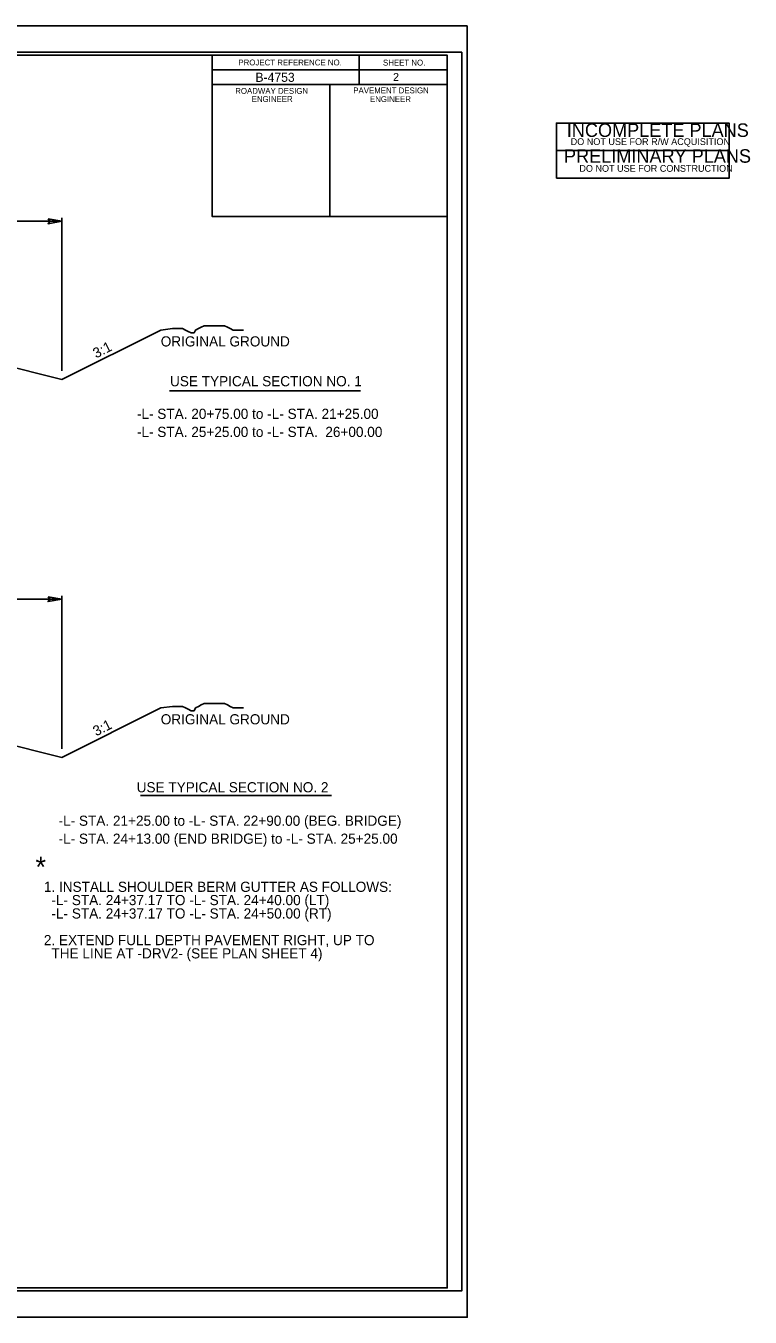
# Model space of a CAD drawing. Extents: x 1804008 to 1804260, y 659269 to 659379.
# Drawn here: x 1804198.7 to 1804260.4, y 659269.4 to 659379.4 of the extents above; entities that cross this region are included whole.
import ezdxf

# ---------------------------------------------------------------- set-up
doc = ezdxf.new("R2010")
doc.units = 0
for name, color, linetype in [('Old_Level_1', 7, 'Continuous'), ('Prop Dimension', 7, 'Continuous'), ('Sheet Cutting Line CELL', 7, 'Continuous'), ('Sheet Data Field CELL', 7, 'Continuous'), ('Sheet Plot Border Inside CELL', 7, 'Continuous'), ('Sheet Plot Border Outside CELL', 7, 'Continuous'), ('Sheet Sticker Incomplete CELL', 7, 'Continuous'), ('Sheet Sticker Preliminary CELL', 7, 'Continuous'), ('Sheet Typical CELL', 7, 'Continuous'), ('Typical Hinge Slope Arterial CELL', 7, 'Continuous'), ('Typical Terminator CELL', 7, 'Continuous')]:
    doc.layers.add(name, color=color, linetype=linetype)

msp = doc.modelspace()

# ---------------------------------------------------------------- linework, layer by layer
at = {"layer": 'Old_Level_1'}
for p, q in [((1804189.79, 659352.24), (1804201.79, 659349.24)), ((1804189.79, 659320.04), (1804201.79, 659317.04))]:
    msp.add_line(p, q, dxfattribs=at)
at = {"layer": 'Prop Dimension'}
for p, q in [((1804189.79, 659362.71), (1804201.79, 659362.71)), ((1804201.79, 659349.95), (1804201.79, 659363.01)), ((1804210.95, 659348.27), (1804227.21, 659348.27)), ((1804189.79, 659330.52), (1804201.79, 659330.52)), ((1804201.79, 659317.76), (1804201.79, 659330.81)), ((1804208.47, 659313.78), (1804224.73, 659313.78))]:
    msp.add_line(p, q, dxfattribs=at)
at = {"layer": 'Sheet Cutting Line CELL'}
for p, q in [((1804236.29, 659379.35), (1804067.89, 659379.35)), ((1804067.89, 659269.35), (1804236.29, 659269.35))]:
    msp.add_line(p, q, dxfattribs=at)
at = {"layer": 'Sheet Plot Border Inside CELL'}
msp.add_lwpolyline([(1804235.84, 659377.11), (1804069.19, 659377.11), (1804069.19, 659271.6), (1804235.84, 659271.6)], close=True, dxfattribs=at)
at = {"layer": 'Sheet Plot Border Outside CELL'}
msp.add_lwpolyline([(1804236.29, 659379.35), (1804067.89, 659379.35), (1804067.89, 659269.35), (1804236.29, 659269.35)], close=True, dxfattribs=at)
at = {"layer": 'Sheet Sticker Incomplete CELL'}
msp.add_lwpolyline([(1804243.88, 659368.72), (1804243.88, 659371.07), (1804258.58, 659371.07), (1804258.58, 659368.72)], close=True, dxfattribs=at)
at = {"layer": 'Sheet Sticker Preliminary CELL'}
msp.add_lwpolyline([(1804243.88, 659366.37), (1804243.88, 659368.72), (1804258.58, 659368.72), (1804258.58, 659366.37)], close=True, dxfattribs=at)
at = {"layer": 'Sheet Typical CELL'}
for p, q in [((1804227.09, 659376.85), (1804227.09, 659374.35)), ((1804214.59, 659375.6), (1804234.59, 659375.6)), ((1804224.59, 659374.35), (1804224.59, 659363.1))]:
    msp.add_line(p, q, dxfattribs=at)
for points in [[(1804234.59, 659376.85), (1804084.59, 659376.85), (1804084.59, 659271.85), (1804234.59, 659271.85)], [(1804214.59, 659376.85), (1804234.59, 659376.85), (1804234.59, 659374.35), (1804214.59, 659374.35)], [(1804214.59, 659374.35), (1804224.59, 659374.35), (1804224.59, 659363.1), (1804214.59, 659363.1)], [(1804224.59, 659374.35), (1804234.59, 659374.35), (1804234.59, 659363.1), (1804224.59, 659363.1)]]:
    msp.add_lwpolyline(points, close=True, dxfattribs=at)
at = {"layer": 'Typical Hinge Slope Arterial CELL'}
for p, q in [((1804210.2, 659353.44), (1804201.79, 659349.24)), ((1804210.2, 659321.25), (1804201.79, 659317.04))]:
    msp.add_line(p, q, dxfattribs=at)
for points in [[(1804210.2, 659353.44), (1804211.19, 659353.57), (1804211.44, 659353.57), (1804211.81, 659353.57), (1804212.05, 659353.57), (1804212.3, 659353.44), (1804212.54, 659353.32), (1804212.79, 659353.2), (1804213.04, 659353.2), (1804213.16, 659353.44), (1804213.41, 659353.57), (1804213.65, 659353.69), (1804213.9, 659353.81), (1804214.15, 659353.81), (1804214.39, 659353.81), (1804214.64, 659353.81), (1804214.89, 659353.81), (1804215.13, 659353.81), (1804215.38, 659353.81), (1804215.63, 659353.81), (1804215.87, 659353.69), (1804216.12, 659353.57), (1804216.36, 659353.44), (1804216.73, 659353.44), (1804216.98, 659353.44), (1804217.23, 659353.44)], [(1804210.2, 659321.25), (1804211.19, 659321.37), (1804211.44, 659321.37), (1804211.81, 659321.37), (1804212.05, 659321.37), (1804212.3, 659321.25), (1804212.54, 659321.13), (1804212.79, 659321), (1804213.04, 659321), (1804213.16, 659321.25), (1804213.41, 659321.37), (1804213.65, 659321.5), (1804213.9, 659321.62), (1804214.15, 659321.62), (1804214.39, 659321.62), (1804214.64, 659321.62), (1804214.89, 659321.62), (1804215.13, 659321.62), (1804215.38, 659321.62), (1804215.63, 659321.62), (1804215.87, 659321.5), (1804216.12, 659321.37), (1804216.36, 659321.25), (1804216.73, 659321.25), (1804216.98, 659321.25), (1804217.23, 659321.25)]]:
    msp.add_lwpolyline(points, dxfattribs=at)
at = {"layer": 'Typical Terminator CELL'}
for points in [[(1804200.62, 659362.91), (1804201.79, 659362.71), (1804200.61, 659362.5), (1804200.76, 659362.71)], [(1804200.62, 659330.72), (1804201.79, 659330.52), (1804200.61, 659330.31), (1804200.76, 659330.52)]]:
    msp.add_lwpolyline(points, close=True, dxfattribs=at)

# ---------------------------------------------------------------- texts
at = {"layer": 'Old_Level_1'}
for s, height, p in [('USE TYPICAL SECTION NO. 1', 0.865, (1804210.99, 659348.65)), ('-L- STA. 20+75.00 to -L- STA. 21+25.00', 0.865, (1804208.17, 659345.87)), ('-L- STA. 25+25.00 to -L- STA.  26+00.00', 0.865, (1804208.17, 659344.33)), ('-L- STA. 21+25.00 to -L- STA. 22+90.00 (BEG. BRIDGE)', 0.865, (1804201.5, 659311.21)), ('-L- STA. 24+13.00 (END BRIDGE) to -L- STA. 25+25.00', 0.865, (1804201.5, 659309.68)), ('*', 1.73, (1804199.53, 659306.84)), ('1. INSTALL SHOULDER BERM GUTTER AS FOLLOWS:', 0.865, (1804200.25, 659305.58)), ('  -L- STA. 24+37.17 TO -L- STA. 24+40.00 (LT)', 0.865, (1804200.25, 659304.45)), ('  -L- STA. 24+37.17 TO -L- STA. 24+50.00 (RT)', 0.865, (1804200.25, 659303.31)), ('2. EXTEND FULL DEPTH PAVEMENT RIGHT, UP TO ', 0.865, (1804200.25, 659301.04)), ('  THE LINE AT -DRV2- (SEE PLAN SHEET 4)', 0.865, (1804200.25, 659299.91))]:
    msp.add_text(s, height=height, dxfattribs=at).set_placement(p)
at = {"layer": 'Prop Dimension'}
msp.add_text('USE TYPICAL SECTION NO. 2', height=0.865, dxfattribs=at).set_placement((1804208.15, 659314.06))
at = {"layer": 'Sheet Data Field CELL'}
for s, height, p in [('B-4753   ', 0.775, (1804218.26, 659374.58)), ('2  ', 0.675, (1804229.98, 659374.66))]:
    msp.add_text(s, height=height, dxfattribs=at).set_placement(p)
at = {"layer": 'Sheet Sticker Incomplete CELL'}
for s, height, p in [('INCOMPLETE PLANS', 1.152, (1804244.77, 659369.89)), ('DO NOT USE FOR R/W ACQUISITION', 0.576, (1804245.1, 659369.2))]:
    msp.add_text(s, height=height, dxfattribs=at).set_placement(p)
at = {"layer": 'Sheet Sticker Preliminary CELL'}
for s, height, p in [('PRELIMINARY PLANS', 1.152, (1804244.53, 659367.69)), ('DO NOT USE FOR CONSTRUCTION', 0.576, (1804245.84, 659366.92)), ('DO NOT USE FOR CONSTRUCTION', 0.576, (1804245.84, 659366.92))]:
    msp.add_text(s, height=height, dxfattribs=at).set_placement(p)
at = {"layer": 'Sheet Typical CELL'}
for s, p in [('PROJECT REFERENCE NO.', (1804216.81, 659375.98)), ('SHEET NO.', (1804229.12, 659375.97)), ('PAVEMENT DESIGN', (1804226.59, 659373.6)), ('ROADWAY DESIGN', (1804216.54, 659373.56)), ('ENGINEER', (1804217.94, 659372.87)), ('ENGINEER', (1804228.01, 659372.86))]:
    msp.add_text(s, height=0.5, dxfattribs=at).set_placement(p)
at = {"layer": 'Typical Hinge Slope Arterial CELL'}
for p in [(1804204.69, 659351.01), (1804204.69, 659318.82)]:
    msp.add_text('3:1', height=0.865, rotation=26.565, dxfattribs=at).set_placement(p)
for p in [(1804210.2, 659352.04), (1804210.2, 659319.85)]:
    msp.add_text('ORIGINAL GROUND', height=0.865, dxfattribs=at).set_placement(p)

doc.saveas('drawing.dxf')
